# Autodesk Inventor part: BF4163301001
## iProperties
Shininess: 64.0
Angle Display Precision: 2
Document Length Units: 11272
Document Angle Units: 11279
Document Time Units: 11290
Document Mass Units: 11286
Document Length Units Precision: 3
Document Angle Units Precision: 2
Created: 2003-05
Part Number: BF4163301001
Material: Bronze, Soft Tin
Description: 1/4 x 1/8 BUSHING, REDUCING, 125 LB RED BRASS, NPT
Vendor: BF4163301001
Document SubType Name: Modeling
Designer: RCOPE
Density: 8.874
Volumn: 1.0496913662066631
Area: 12.761898175815361
PropertySet Name: Model Information
Control State: 0
Master: False
Checked Out: False
Title: BUSHING, REDUCING, 125 LB RED BRASS, NPT
Author: RCOPE
Revision Number: 0
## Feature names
1. Extrusion1
2. Extrusion2
3. Extrusion3
4. Extrusion4
5. Extrusion5
